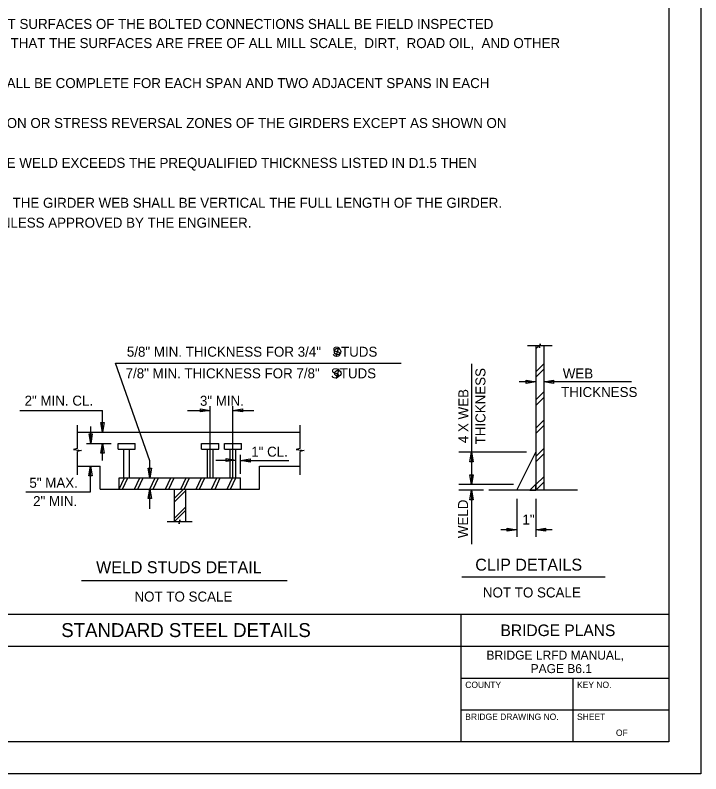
# Model space of a CAD drawing. Extents: x 0 to 47.8, y 0 to 23.5.
# Drawn here: x 23.27 to 34, y 0 to 11.88 of the extents above; entities that cross this region are included whole.
import ezdxf

# ---------------------------------------------------------------- set-up
doc = ezdxf.new("R2010")
doc.units = 0
for name, color, linetype in [('BORDER_ANNO_Cutsheet', 7, 'Continuous'), ('BRDG_ANNO_Anno-Sheet', 7, 'Continuous'), ('BRDG_ANNO_General-Notes', 7, 'Continuous'), ('BRDG_BASE_Dtlctrln', 7, 'Continuous'), ('BRDG_BASE_Obj-Line', 7, 'Continuous'), ('BRDG_BASE_Pattern', 7, 'Continuous')]:
    doc.layers.add(name, color=color, linetype=linetype)

msp = doc.modelspace()

# ---------------------------------------------------------------- linework, layer by layer
at = {"layer": 'BORDER_ANNO_Cutsheet'}
msp.add_lwpolyline([(0, 22), (34, 22), (34, 0), (0, 0)], close=True, dxfattribs=at)
at = {"layer": 'BRDG_ANNO_Anno-Sheet'}
for p, q in [((19.25, 2.5), (33.5, 2.5)), ((30.25, 0.5), (30.25, 2.5)), ((22.25, 2), (30.25, 2)), ((30.25, 2), (33.5, 2)), ((30.25, 1.5), (33.5, 1.5)), ((32, 0.5), (32, 1.5)), ((30.25, 1), (33.5, 1))]:
    msp.add_line(p, q, dxfattribs=at)
msp.add_lwpolyline([(1.5, 21.5), (33.5, 21.5), (33.5, 0.5), (1.5, 0.5)], close=True, dxfattribs=at)
at = {"layer": 'BRDG_ANNO_General-Notes'}
for p, q in [((28.291, 6.531), (28.333, 6.687)), ((25.374, 4.901), (24.834, 6.429)), ((24.834, 6.429), (29.311, 6.429)), ((30.41, 6.419), (30.41, 5.036)), ((28.297, 6.191), (28.339, 6.347)), ((31.416, 6.137), (31.156, 6.137)), ((31.266, 6.112), (31.266, 6.162)), ((31.266, 6.162), (31.416, 6.137)), ((31.416, 6.137), (31.266, 6.112)), ((31.542, 6.137), (31.692, 6.162)), ((32.915, 6.137), (31.542, 6.137)), ((31.692, 6.112), (31.542, 6.137)), ((31.692, 6.162), (31.692, 6.112)), ((26.168, 5.665), (26.168, 5.715)), ((26.168, 5.715), (26.318, 5.69)), ((26.674, 5.69), (26.824, 5.715)), ((26.824, 5.715), (26.824, 5.665)), ((23.339, 5.69), (24.634, 5.69)), ((24.634, 5.351), (24.634, 5.69)), ((25.965, 5.69), (26.318, 5.69)), ((26.318, 5.69), (26.168, 5.665)), ((26.674, 5.69), (27.003, 5.69)), ((26.824, 5.665), (26.674, 5.69)), ((24.609, 5.501), (24.659, 5.501)), ((24.634, 5.351), (24.609, 5.501)), ((24.659, 5.501), (24.634, 5.351)), ((24.448, 5.171), (24.448, 5.438)), ((24.423, 5.321), (24.473, 5.321)), ((24.448, 5.171), (24.423, 5.321)), ((24.473, 5.321), (24.448, 5.171)), ((24.38, 5.171), (24.766, 5.171)), ((24.609, 5.021), (24.634, 5.171)), ((24.634, 4.904), (24.634, 5.171)), ((24.634, 5.171), (24.659, 5.021)), ((24.659, 5.021), (24.609, 5.021)), ((26.793, 4.695), (26.793, 4.996)), ((26.793, 4.705), (26.793, 4.996)), ((31.27, 5.036), (30.212, 5.036)), ((30.385, 4.886), (30.41, 5.036)), ((30.41, 5.036), (30.41, 4.531)), ((30.41, 5.036), (30.435, 4.886)), ((25.374, 4.634), (25.374, 4.901)), ((26.409, 4.913), (26.719, 4.913)), ((26.569, 4.888), (26.569, 4.938)), ((26.569, 4.938), (26.719, 4.913)), ((26.719, 4.913), (26.569, 4.888)), ((26.793, 4.906), (26.943, 4.931)), ((26.793, 4.906), (27.55, 4.906)), ((26.943, 4.881), (26.793, 4.906)), ((26.943, 4.931), (26.943, 4.881)), ((30.435, 4.886), (30.385, 4.886)), ((24.42, 4.665), (24.445, 4.815)), ((24.445, 4.416), (24.445, 4.815)), ((24.445, 4.815), (24.47, 4.665)), ((25.349, 4.784), (25.399, 4.784)), ((25.374, 4.634), (25.349, 4.784)), ((25.399, 4.784), (25.374, 4.634)), ((24.47, 4.665), (24.42, 4.665)), ((30.385, 4.681), (30.435, 4.681)), ((30.41, 4.531), (30.385, 4.681)), ((30.435, 4.681), (30.41, 4.531)), ((31.066, 4.531), (30.211, 4.531)), ((23.432, 4.416), (24.445, 4.416)), ((25.349, 4.309), (25.374, 4.459)), ((25.374, 4.147), (25.374, 4.459)), ((25.374, 4.459), (25.399, 4.309)), ((30.598, 4.442), (30.211, 4.442)), ((30.385, 4.292), (30.41, 4.442)), ((30.41, 4.442), (30.41, 3.598)), ((30.41, 4.442), (30.435, 4.292)), ((25.399, 4.309), (25.349, 4.309)), ((30.435, 4.292), (30.385, 4.292)), ((31.12, 4.306), (31.12, 3.709)), ((31.417, 4.306), (31.417, 3.709)), ((31.12, 3.822), (30.868, 3.822)), ((30.97, 3.797), (30.97, 3.847)), ((30.97, 3.847), (31.12, 3.822)), ((31.12, 3.822), (30.97, 3.797)), ((31.417, 3.822), (31.567, 3.847)), ((31.671, 3.822), (31.417, 3.822)), ((31.567, 3.797), (31.417, 3.822)), ((31.567, 3.847), (31.567, 3.797)), ((24.303, 3.028), (27.525, 3.028)), ((30.257, 3.083), (32.5, 3.083))]:
    msp.add_line(p, q, dxfattribs=at)
for centre in [(28.313, 6.61), (28.319, 6.27)]:
    msp.add_circle(centre, 0.0507, dxfattribs=at)
at = {"layer": 'BRDG_BASE_Dtlctrln'}
for p, q in [((26.318, 4.636), (26.318, 5.754)), ((26.674, 4.636), (26.674, 5.754))]:
    msp.add_line(p, q, dxfattribs=at)
at = {"layer": 'BRDG_BASE_Obj-Line'}
for p, q in [((31.468, 6.701), (31.284, 6.701)), ((31.417, 6.701), (31.417, 4.443)), ((31.468, 6.701), (31.476, 6.669)), ((31.476, 6.669), (31.484, 6.732)), ((31.484, 6.732), (31.491, 6.701)), ((31.675, 6.701), (31.491, 6.701)), ((31.542, 6.701), (31.542, 4.443)), ((24.24, 5.094), (24.24, 5.461)), ((24.24, 5.351), (27.727, 5.351)), ((27.727, 5.094), (27.727, 5.461)), ((24.878, 5.082), (24.878, 5.171)), ((24.878, 5.171), (25.145, 5.171)), ((25.145, 5.082), (25.145, 5.171)), ((26.185, 5.082), (26.185, 5.171)), ((26.185, 5.171), (26.452, 5.171)), ((26.452, 5.082), (26.452, 5.171)), ((26.541, 5.082), (26.541, 5.171)), ((26.541, 5.171), (26.808, 5.171)), ((26.808, 5.082), (26.808, 5.171)), ((24.24, 5.094), (24.177, 5.078)), ((24.177, 5.078), (24.302, 5.062)), ((24.302, 5.062), (24.24, 5.047)), ((24.24, 4.68), (24.24, 5.047)), ((24.878, 5.082), (25.145, 5.082)), ((24.967, 4.636), (24.967, 5.082)), ((25.056, 4.636), (25.056, 5.082)), ((26.185, 5.082), (26.452, 5.082)), ((26.274, 4.636), (26.274, 5.082)), ((26.363, 4.636), (26.363, 5.082)), ((26.541, 5.082), (26.808, 5.082)), ((26.63, 4.636), (26.63, 5.082)), ((26.719, 4.636), (26.719, 5.082)), ((27.727, 5.094), (27.664, 5.078)), ((27.664, 5.078), (27.789, 5.062)), ((27.789, 5.062), (27.727, 5.047)), ((27.727, 4.68), (27.727, 5.047)), ((31.12, 4.443), (31.417, 5.036)), ((24.24, 4.817), (24.596, 4.817)), ((24.596, 4.458), (24.596, 4.817)), ((27.09, 4.817), (27.727, 4.817)), ((27.09, 4.458), (27.09, 4.815)), ((24.893, 4.636), (26.793, 4.636)), ((24.893, 4.458), (24.893, 4.636)), ((26.793, 4.458), (26.793, 4.636)), ((24.596, 4.458), (27.09, 4.458)), ((25.754, 4.458), (25.754, 3.943)), ((25.932, 4.458), (25.932, 3.943)), ((32.067, 4.442), (30.682, 4.442)), ((25.827, 3.943), (25.643, 3.943)), ((25.827, 3.943), (25.835, 3.912)), ((25.835, 3.912), (25.842, 3.975)), ((25.842, 3.975), (25.85, 3.943)), ((26.034, 3.943), (25.85, 3.943))]:
    msp.add_line(p, q, dxfattribs=at)
msp.add_lwpolyline([(31.417, 4.443), (31.417, 4.537), (31.323, 4.443), (31.417, 4.443)], dxfattribs=at)
at = {"layer": 'BRDG_BASE_Pattern'}
for p, q in [((31.417, 6.653), (31.465, 6.701)), ((31.417, 6.295), (31.542, 6.42)), ((31.417, 6.211), (31.542, 6.336)), ((31.417, 5.853), (31.542, 5.978)), ((31.417, 5.769), (31.542, 5.894)), ((31.417, 5.411), (31.542, 5.536)), ((31.417, 5.327), (31.542, 5.452)), ((31.417, 4.969), (31.542, 5.094)), ((31.417, 4.885), (31.542, 5.01)), ((24.893, 4.458), (24.976, 4.636)), ((24.946, 4.458), (25.029, 4.636)), ((25.134, 4.458), (25.218, 4.636)), ((25.187, 4.458), (25.27, 4.636)), ((25.376, 4.458), (25.459, 4.636)), ((25.428, 4.458), (25.511, 4.636)), ((25.617, 4.458), (25.7, 4.636)), ((25.67, 4.458), (25.753, 4.636)), ((25.859, 4.458), (25.942, 4.636)), ((25.911, 4.458), (25.994, 4.636)), ((26.1, 4.458), (26.183, 4.636)), ((26.152, 4.458), (26.236, 4.636)), ((26.341, 4.458), (26.424, 4.636)), ((26.394, 4.458), (26.477, 4.636)), ((26.583, 4.458), (26.666, 4.636)), ((26.635, 4.458), (26.718, 4.636)), ((31.417, 4.527), (31.542, 4.652)), ((31.417, 4.443), (31.542, 4.568)), ((25.754, 4.31), (25.903, 4.458)), ((25.754, 4.253), (25.932, 4.431)), ((25.754, 3.999), (25.932, 4.177)), ((25.754, 3.943), (25.932, 4.121))]:
    msp.add_line(p, q, dxfattribs=at)

# ---------------------------------------------------------------- texts
at = {"layer": 'BRDG_ANNO_Anno-Sheet'}
for s, height, p in [('STANDARD STEEL DETAILS', 0.21813, (23.987, 2.141)), ('BRIDGE PLANS', 0.18187, (30.864, 2.156)), ('BRIDGE LRFD MANUAL,', 0.14062, (30.644, 1.788)), ('PAGE B6.1', 0.1406, (31.335, 1.577)), ('COUNTY', 0.0994, (30.312, 1.344)), ('KEY NO.', 0.0994, (32.062, 1.344)), ('BRIDGE DRAWING NO.', 0.09937, (30.312, 0.844)), ('SHEET', 0.0994, (32.062, 0.844)), ('OF', 0.0994, (32.671, 0.594))]:
    msp.add_text(s, height=height, dxfattribs=at).set_placement(p)
at = {"layer": 'BRDG_ANNO_General-Notes'}
for s, height, p in [('(INCLUDED IN THE SHEAR PLANE).  ALL CONTACT SURFACES OF THE BOLTED CONNECTIONS SHALL BE FIELD INSPECTED', 0.15625, (18.19, 11.662)), ('IMMEDIATELY PRIOR TO ASSEMBLY TO ENSURE THAT THE SURFACES ARE FREE OF ALL MILL SCALE,  DIRT,  ROAD OIL,  AND OTHER', 0.15625, (18.19, 11.362)), ('4. STEEL GIRDER SUPERSTRUCTURE ERECTION SHALL BE COMPLETE FOR EACH SPAN AND TWO ADJACENT SPANS IN EACH', 0.15625, (17.815, 10.736)), ('5. NO WELDING SHALL BE PERMITTED IN THE TENSION OR STRESS REVERSAL ZONES OF THE GIRDERS EXCEPT AS SHOWN ON', 0.15625, (17.815, 10.111)), ('6. IF THE PLATE THICKNESS FOR PARALLEL GROOVE WELD EXCEEDS THE PREQUALIFIED THICKNESS LISTED IN D1.5 THEN', 0.15625, (17.815, 9.487)), ('7. UNDER FULL DEAD LOAD AND DECK SHRINKAGE,  THE GIRDER WEB SHALL BE VERTICAL THE FULL LENGTH OF THE GIRDER.', 0.15625, (17.815, 8.862)), ('8. NO ADDITIONAL SHOP SPLICES ARE ALLOWED UNLESS APPROVED BY THE ENGINEER.', 0.15625, (17.815, 8.55)), ('5/8" MIN. THICKNESS FOR 3/4"   STUDS', 0.15625, (25.014, 6.53)), ('7/8" MIN. THICKNESS FOR 7/8"   STUDS', 0.15625, (24.994, 6.192)), ('WEB', 0.1562, (31.839, 6.19)), ('THICKNESS', 0.1562, (31.812, 5.899)), ('2" MIN. CL.', 0.15625, (23.413, 5.764)), ('3" MIN.', 0.1562, (26.158, 5.762)), ('1" CL.', 0.1562, (26.961, 4.965)), ('5" MAX.', 0.1562, (23.488, 4.478)), ('2" MIN.', 0.1562, (23.546, 4.192)), ('1"', 0.1562, (31.207, 3.903)), ('WELD STUDS DETAIL', 0.1875, (24.533, 3.141)), ('CLIP DETAILS', 0.1875, (30.469, 3.181)), ('NOT TO SCALE', 0.15625, (25.133, 2.697)), ('NOT TO SCALE', 0.15625, (30.588, 2.761))]:
    msp.add_text(s, height=height, dxfattribs=at).set_placement(p)
for s, p in [('THICKNESS', (30.628, 5.158)), ('4 X WEB', (30.361, 5.177)), ('WELD', (30.355, 3.69))]:
    msp.add_text(s, height=0.1562, rotation=90, dxfattribs=at).set_placement(p)

doc.saveas('drawing.dxf')
